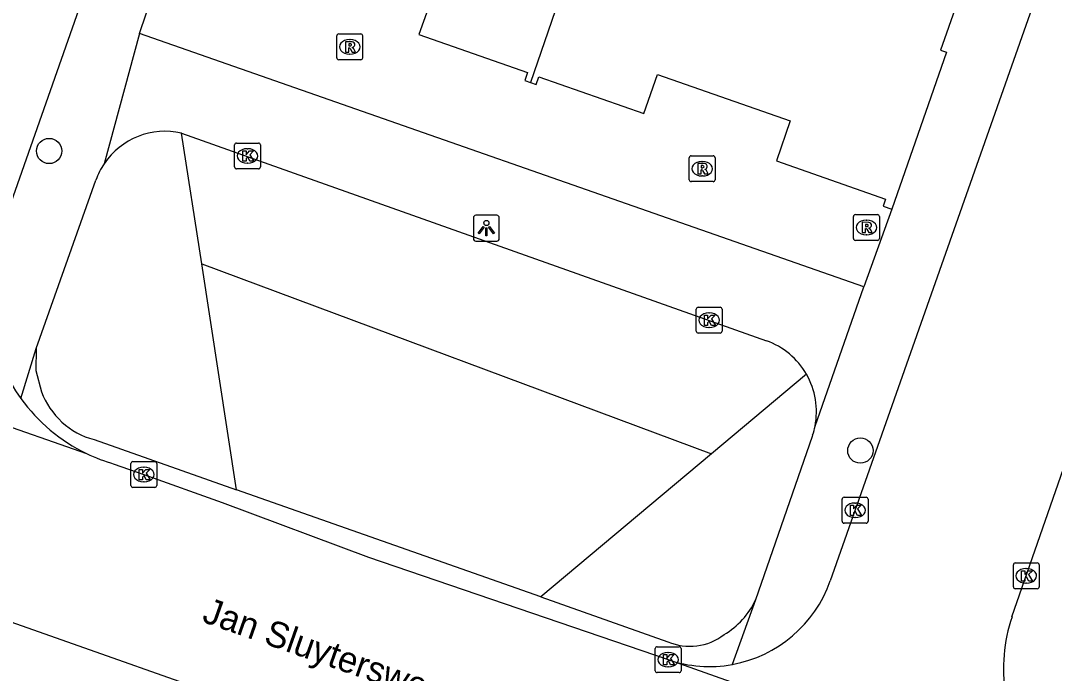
# Model space of a CAD drawing. Extents: x 163268 to 164360, y 381529 to 382285.
# Drawn here: x 163770.78 to 163810.76, y 381848.7 to 381873.93 of the extents above; entities that cross this region are included whole.
import ezdxf

# ---------------------------------------------------------------- set-up
doc = ezdxf.new("R2010")
doc.units = 0
for name, color, linetype in [('IMGEO_Boom', 7, 'Continuous'), ('IMGEO_Groenvoorziening', 7, 'Continuous'), ('IMGEO_Kolk', 7, 'Continuous'), ('IMGEO_Lichtpunt', 7, 'Continuous'), ('IMGEO_Openbare_ruimte_label', 7, 'Continuous'), ('IMGEO_Pand', 7, 'Continuous'), ('IMGEO_Rijbaan_lokaal_open', 7, 'Continuous'), ('IMGEO_Rioolput', 7, 'Continuous'), ('IMGEO_Voetpad_open', 7, 'Continuous')]:
    doc.layers.add(name, color=color, linetype=linetype)

msp = doc.modelspace()

# ---------------------------------------------------------------- linework, layer by layer
at = {"layer": 'IMGEO_Boom'}
for centre in [(163771.878, 381868.895), (163803.255, 381857.31)]:
    msp.add_circle(centre, 0.489, dxfattribs=at)
at = {"layer": 'IMGEO_Groenvoorziening'}
for points in [[(163777.78, 381864.53), (163777.001, 381869.584)], [(163779.121, 381855.795), (163777.78, 381864.53)], [(163777.78, 381864.53), (163797.5, 381857.188)], [(163801.172, 381860.26), (163797.5, 381857.188)], [(163797.5, 381857.188), (163790.89, 381851.653)]]:
    msp.add_lwpolyline(points, dxfattribs=at)
at = {"layer": 'IMGEO_Kolk'}
for p, q in [((163779.05, 381868.277), (163779.05, 381869.129)), ((163779.125, 381869.203), (163779.977, 381869.203)), ((163779.538, 381868.983), (163779.563, 381868.983)), ((163780.051, 381869.129), (163780.051, 381868.277)), ((163779.977, 381868.203), (163779.125, 381868.203)), ((163779.561, 381868.423), (163779.536, 381868.423)), ((163796.904, 381861.927), (163796.904, 381862.779)), ((163796.979, 381862.853), (163797.831, 381862.853)), ((163797.392, 381862.633), (163797.417, 381862.633)), ((163797.905, 381862.779), (163797.905, 381861.927)), ((163797.415, 381862.073), (163797.39, 381862.073)), ((163797.831, 381861.853), (163796.979, 381861.853)), ((163775.116, 381856.885), (163775.968, 381856.885)), ((163775.041, 381855.959), (163775.041, 381856.811)), ((163775.529, 381856.665), (163775.554, 381856.665)), ((163776.042, 381856.811), (163776.042, 381855.959)), ((163775.552, 381856.105), (163775.527, 381856.105)), ((163775.968, 381855.885), (163775.116, 381855.885)), ((163802.55, 381854.577), (163802.55, 381855.429)), ((163802.625, 381855.503), (163803.477, 381855.503)), ((163803.038, 381855.283), (163803.063, 381855.283)), ((163803.551, 381855.429), (163803.551, 381854.577)), ((163803.477, 381854.503), (163802.625, 381854.503)), ((163803.061, 381854.723), (163803.036, 381854.723)), ((163809.172, 381852.04), (163809.172, 381852.892)), ((163809.247, 381852.966), (163810.099, 381852.966)), ((163810.173, 381852.892), (163810.173, 381852.04)), ((163809.66, 381852.746), (163809.685, 381852.746)), ((163809.683, 381852.186), (163809.658, 381852.186)), ((163810.099, 381851.966), (163809.247, 381851.966)), ((163795.395, 381849.726), (163796.247, 381849.726)), ((163795.32, 381848.8), (163795.32, 381849.652)), ((163795.808, 381849.506), (163795.833, 381849.506)), ((163796.321, 381849.652), (163796.321, 381848.8)), ((163795.831, 381848.946), (163795.806, 381848.946)), ((163796.247, 381848.726), (163795.395, 381848.726))]:
    msp.add_line(p, q, dxfattribs=at)
for points in [[(163779.05, 381868.277), (163779.05, 381869.129)], [(163779.125, 381869.203), (163779.977, 381869.203)], [(163779.371, 381868.903), (163779.494, 381868.903), (163779.494, 381868.752), (163779.624, 381868.903), (163779.788, 381868.903), (163779.642, 381868.752), (163779.795, 381868.503), (163779.643, 381868.503), (163779.558, 381868.667), (163779.494, 381868.6), (163779.494, 381868.503), (163779.371, 381868.503), (163779.371, 381868.903)], [(163780.051, 381869.129), (163780.051, 381868.277)], [(163779.977, 381868.203), (163779.125, 381868.203)], [(163796.904, 381861.927), (163796.904, 381862.779)], [(163796.979, 381862.853), (163797.831, 381862.853)], [(163797.225, 381862.553), (163797.348, 381862.553), (163797.348, 381862.402), (163797.478, 381862.553), (163797.642, 381862.553), (163797.496, 381862.402), (163797.649, 381862.153), (163797.497, 381862.153), (163797.412, 381862.317), (163797.348, 381862.25), (163797.348, 381862.153), (163797.225, 381862.153), (163797.225, 381862.553)], [(163797.905, 381862.779), (163797.905, 381861.927)], [(163797.831, 381861.853), (163796.979, 381861.853)], [(163775.116, 381856.885), (163775.968, 381856.885)], [(163775.041, 381855.959), (163775.041, 381856.811)], [(163775.362, 381856.585), (163775.485, 381856.585), (163775.485, 381856.434), (163775.615, 381856.585), (163775.779, 381856.585), (163775.633, 381856.434), (163775.786, 381856.185), (163775.634, 381856.185), (163775.549, 381856.349), (163775.485, 381856.282), (163775.485, 381856.185), (163775.362, 381856.185), (163775.362, 381856.585)], [(163776.042, 381856.811), (163776.042, 381855.959)], [(163775.968, 381855.885), (163775.116, 381855.885)], [(163802.55, 381854.577), (163802.55, 381855.429)], [(163802.625, 381855.503), (163803.477, 381855.503)], [(163803.551, 381855.429), (163803.551, 381854.577)], [(163802.871, 381855.203), (163802.994, 381855.203), (163802.994, 381855.052), (163803.124, 381855.203), (163803.288, 381855.203), (163803.142, 381855.052), (163803.295, 381854.803), (163803.143, 381854.803), (163803.058, 381854.967), (163802.994, 381854.9), (163802.994, 381854.803), (163802.871, 381854.803), (163802.871, 381855.203)], [(163803.477, 381854.503), (163802.625, 381854.503)], [(163809.172, 381852.04), (163809.172, 381852.892)], [(163809.247, 381852.966), (163810.099, 381852.966)], [(163810.173, 381852.892), (163810.173, 381852.04)], [(163809.493, 381852.666), (163809.616, 381852.666), (163809.616, 381852.515), (163809.746, 381852.666), (163809.91, 381852.666), (163809.764, 381852.515), (163809.917, 381852.266), (163809.765, 381852.266), (163809.68, 381852.43), (163809.616, 381852.363), (163809.616, 381852.266), (163809.493, 381852.266), (163809.493, 381852.666)], [(163810.099, 381851.966), (163809.247, 381851.966)], [(163795.395, 381849.726), (163796.247, 381849.726)], [(163795.32, 381848.8), (163795.32, 381849.652)], [(163795.641, 381849.426), (163795.764, 381849.426), (163795.764, 381849.275), (163795.894, 381849.426), (163796.058, 381849.426), (163795.912, 381849.275), (163796.065, 381849.026), (163795.913, 381849.026), (163795.828, 381849.19), (163795.764, 381849.123), (163795.764, 381849.026), (163795.641, 381849.026), (163795.641, 381849.426)], [(163796.321, 381849.652), (163796.321, 381848.8)], [(163796.247, 381848.726), (163795.395, 381848.726)]]:
    msp.add_lwpolyline(points, dxfattribs=at)
for centre, start, end in [((163779.127, 381869.127), 91.552, 178.448), ((163779.127, 381869.127), 91.552, 178.448), ((163779.975, 381869.127), 1.552, 88.448), ((163779.975, 381869.127), 1.552, 88.448), ((163779.127, 381868.279), 181.552, 268.448), ((163779.127, 381868.279), 181.552, 268.448), ((163779.975, 381868.279), 271.552, 358.448), ((163779.975, 381868.279), 271.552, 358.448), ((163796.981, 381862.777), 91.552, 178.448), ((163796.981, 381862.777), 91.552, 178.448), ((163797.829, 381862.777), 1.552, 88.448), ((163797.829, 381862.777), 1.552, 88.448), ((163796.981, 381861.929), 181.552, 268.448), ((163796.981, 381861.929), 181.552, 268.448), ((163797.829, 381861.929), 271.552, 358.448), ((163797.829, 381861.929), 271.552, 358.448), ((163775.118, 381856.809), 91.552, 178.448), ((163775.118, 381856.809), 91.552, 178.448), ((163775.966, 381856.809), 1.552, 88.448), ((163775.966, 381856.809), 1.552, 88.448), ((163775.118, 381855.961), 181.552, 268.448), ((163775.118, 381855.961), 181.552, 268.448), ((163775.966, 381855.961), 271.552, 358.448), ((163775.966, 381855.961), 271.552, 358.448), ((163802.627, 381855.427), 91.552, 178.448), ((163802.627, 381855.427), 91.552, 178.448), ((163803.475, 381855.427), 1.552, 88.448), ((163803.475, 381855.427), 1.552, 88.448), ((163802.627, 381854.579), 181.552, 268.448), ((163802.627, 381854.579), 181.552, 268.448), ((163803.475, 381854.579), 271.552, 358.448), ((163803.475, 381854.579), 271.552, 358.448), ((163809.249, 381852.89), 91.552, 178.448), ((163809.249, 381852.89), 91.552, 178.448), ((163810.097, 381852.89), 1.552, 88.448), ((163810.097, 381852.89), 1.552, 88.448), ((163809.249, 381852.042), 181.552, 268.448), ((163809.249, 381852.042), 181.552, 268.448), ((163810.097, 381852.042), 271.552, 358.448), ((163810.097, 381852.042), 271.552, 358.448), ((163795.397, 381849.65), 91.552, 178.448), ((163795.397, 381849.65), 91.552, 178.448), ((163796.245, 381849.65), 1.552, 88.448), ((163796.245, 381849.65), 1.552, 88.448), ((163795.397, 381848.802), 181.552, 268.448), ((163795.397, 381848.802), 181.552, 268.448), ((163796.245, 381848.802), 271.552, 358.448), ((163796.245, 381848.802), 271.552, 358.448)]:
    msp.add_arc(centre, 0.0765, start, end, dxfattribs=at)
for centre, major_axis, ratio, start_param, end_param in [((163779.537, 381868.703), (-0.387, 0.002), 0.722429, 4.712389, 7.853982), ((163779.562, 381868.703), (-0.39, 0.002), 0.717154, 1.570796, 4.712389), ((163797.391, 381862.353), (-0.387, 0.002), 0.722429, 4.712389, 7.853982), ((163797.416, 381862.353), (-0.39, 0.002), 0.717154, 1.570796, 4.712389), ((163775.528, 381856.385), (-0.387, 0.002), 0.722429, 4.712389, 7.853982), ((163775.553, 381856.385), (-0.39, 0.002), 0.717154, 1.570796, 4.712389), ((163803.037, 381855.003), (-0.387, 0.002), 0.722429, 4.712389, 7.853982), ((163803.062, 381855.003), (-0.39, 0.002), 0.717154, 1.570796, 4.712389), ((163809.659, 381852.466), (-0.387, 0.002), 0.722429, 4.712389, 7.853982), ((163809.684, 381852.466), (-0.39, 0.002), 0.717154, 1.570796, 4.712389), ((163795.807, 381849.226), (-0.387, 0.002), 0.722429, 4.712389, 7.853982), ((163795.832, 381849.226), (-0.39, 0.002), 0.717154, 1.570796, 4.712389)]:
    msp.add_ellipse(centre, major_axis=major_axis, ratio=ratio, start_param=start_param, end_param=end_param, dxfattribs=at)
at = {"layer": 'IMGEO_Lichtpunt'}
for p, q in [((163788.291, 381866.314), (163788.291, 381865.507)), ((163788.291, 381866.314), (163788.291, 381865.507)), ((163789.193, 381866.409), (163788.385, 381866.409)), ((163789.193, 381866.409), (163788.385, 381866.409)), ((163789.287, 381865.507), (163789.287, 381866.314)), ((163789.287, 381865.507), (163789.287, 381866.314)), ((163788.385, 381865.413), (163789.193, 381865.413)), ((163788.385, 381865.413), (163789.193, 381865.413))]:
    msp.add_line(p, q, dxfattribs=at)
for points in [[(163788.665, 381865.978), (163788.704, 381865.95), (163788.516, 381865.688), (163788.478, 381865.715), (163788.665, 381865.978)], [(163788.767, 381865.93), (163788.814, 381865.93), (163788.814, 381865.608), (163788.767, 381865.608), (163788.767, 381865.93)], [(163788.877, 381865.95), (163788.915, 381865.977), (163789.102, 381865.715), (163789.063, 381865.687), (163788.877, 381865.95)]]:
    msp.add_lwpolyline(points, dxfattribs=at)
msp.add_circle((163788.79, 381866.112), 0.0994, dxfattribs=at)
for centre, start, end in [((163788.385, 381866.314), 90, 180), ((163788.385, 381866.314), 90, 180), ((163789.193, 381866.314), 0, 90), ((163789.193, 381866.314), 0, 90), ((163788.385, 381865.507), 180, 270), ((163788.385, 381865.507), 180, 270), ((163789.193, 381865.507), 270, 0), ((163789.193, 381865.507), 270, 360)]:
    msp.add_arc(centre, 0.0946, start, end, dxfattribs=at)
at = {"layer": 'IMGEO_Pand'}
for points in [[(163793.764, 381881.031), (163790.492, 381871.546)], [(163776.402, 381876.494), (163776.751, 381876.372), (163776.86, 381876.683), (163781.149, 381875.183), (163781.673, 381876.678), (163786.715, 381874.914), (163786.184, 381873.395), (163790.382, 381871.926), (163790.275, 381871.622), (163790.492, 381871.546)], [(163807.537, 381876.168), (163806.358, 381872.797), (163806.591, 381872.716), (163804.468, 381866.646)], [(163790.492, 381871.546), (163790.711, 381871.47), (163790.814, 381871.764), (163794.885, 381870.34), (163795.413, 381871.851), (163800.545, 381870.055), (163800.005, 381868.511), (163804.227, 381867.035), (163804.132, 381866.763), (163804.468, 381866.646)]]:
    msp.add_lwpolyline(points, dxfattribs=at)
at = {"layer": 'IMGEO_Rijbaan_lokaal_open'}
for points in [[(163846.791, 381979.115), (163802.089, 381852.268)], [(163769.681, 381864.823), (163769.977, 381865.691), (163779.141, 381891.761), (163784.6, 381907.284)], [(163842.527, 381825.22), (163708.059, 381872.677), (163706.919, 381873.05)], [(163757.684, 381862.669), (163773.325, 381857.198)], [(163809.12, 381850.886), (163812.108, 381859.471), (163812.258, 381859.902)], [(163774.389, 381856.791), (163775.543, 381856.384), (163778.574, 381855.301), (163784.237, 381853.183), (163795.817, 381849.226)], [(163795.817, 381849.226), (163812.836, 381843.202)]]:
    msp.add_lwpolyline(points, dxfattribs=at)
for centre, radius, start, end in [((163776.262, 381863.284), 6.758, 166.838, 215.882), ((163776.244, 381863.265), 6.732, 215.8375, 244.3077), ((163776.245, 381863.236), 6.707, 244.1954, 253.939), ((163797.416, 381853.914), 4.954, 280.3113, 340.5916), ((163815.134, 381848.864), 6.344, 161.4202, 188.6801), ((163797.418, 381853.912), 4.952, 251.1415, 280.3008)]:
    msp.add_arc(centre, radius, start, end, dxfattribs=at)
at = {"layer": 'IMGEO_Rioolput'}
for p, q in [((163783.004, 381872.496), (163783.004, 381873.348)), ((163783.079, 381873.422), (163783.931, 381873.422)), ((163784.005, 381873.348), (163784.005, 381872.496)), ((163783.492, 381873.202), (163783.517, 381873.202)), ((163783.515, 381872.642), (163783.49, 381872.642)), ((163783.931, 381872.422), (163783.079, 381872.422)), ((163796.635, 381867.783), (163796.635, 381868.635)), ((163796.71, 381868.709), (163797.562, 381868.709)), ((163797.123, 381868.489), (163797.148, 381868.489)), ((163797.636, 381868.635), (163797.636, 381867.783)), ((163797.562, 381867.709), (163796.71, 381867.709)), ((163797.146, 381867.929), (163797.121, 381867.929)), ((163802.988, 381865.511), (163802.988, 381866.363)), ((163803.063, 381866.437), (163803.915, 381866.437)), ((163803.476, 381866.217), (163803.501, 381866.217)), ((163803.989, 381866.363), (163803.989, 381865.511)), ((163803.915, 381865.437), (163803.063, 381865.437)), ((163803.499, 381865.657), (163803.474, 381865.657))]:
    msp.add_line(p, q, dxfattribs=at)
for points in [[(163783.004, 381872.496), (163783.004, 381873.348)], [(163783.079, 381873.422), (163783.931, 381873.422)], [(163784.005, 381873.348), (163784.005, 381872.496)], [(163783.593, 381873.12), (163783.341, 381873.122), (163783.341, 381872.722)], [(163783.341, 381872.722), (163783.465, 381872.722), (163783.465, 381872.884), (163783.476, 381872.884)], [(163783.519, 381873.041), (163783.465, 381873.041), (163783.465, 381872.96)], [(163783.465, 381872.96), (163783.517, 381872.96)], [(163783.523, 381872.855), (163783.594, 381872.722), (163783.734, 381872.722), (163783.669, 381872.848)], [(163783.931, 381872.422), (163783.079, 381872.422)], [(163796.635, 381867.783), (163796.635, 381868.635)], [(163796.71, 381868.709), (163797.562, 381868.709)], [(163797.636, 381868.635), (163797.636, 381867.783)], [(163797.224, 381868.407), (163796.972, 381868.409), (163796.972, 381868.009)], [(163796.972, 381868.009), (163797.096, 381868.009), (163797.096, 381868.171), (163797.107, 381868.171)], [(163797.15, 381868.328), (163797.096, 381868.328), (163797.096, 381868.247)], [(163797.096, 381868.247), (163797.148, 381868.247)], [(163797.154, 381868.142), (163797.225, 381868.009), (163797.365, 381868.009), (163797.3, 381868.135)], [(163797.562, 381867.709), (163796.71, 381867.709)], [(163802.988, 381865.511), (163802.988, 381866.363)], [(163803.063, 381866.437), (163803.915, 381866.437)], [(163803.577, 381866.135), (163803.325, 381866.137), (163803.325, 381865.737)], [(163803.989, 381866.363), (163803.989, 381865.511)], [(163803.325, 381865.737), (163803.449, 381865.737), (163803.449, 381865.899), (163803.46, 381865.899)], [(163803.503, 381866.056), (163803.449, 381866.056), (163803.449, 381865.975)], [(163803.449, 381865.975), (163803.501, 381865.975)], [(163803.507, 381865.87), (163803.578, 381865.737), (163803.718, 381865.737), (163803.653, 381865.863)], [(163803.915, 381865.437), (163803.063, 381865.437)]]:
    msp.add_lwpolyline(points, dxfattribs=at)
for centre, radius, start, end in [((163783.081, 381873.346), 0.0765, 91.552, 178.448), ((163783.081, 381873.346), 0.0765, 91.552, 178.448), ((163783.929, 381873.346), 0.0765, 1.552, 88.448), ((163783.929, 381873.346), 0.0765, 1.552, 88.448), ((163783.475, 381872.831), 0.0533, 26.0293, 88.6989), ((163783.501, 381873.149), 0.19, 274.7715, 282.9687), ((163783.525, 381872.945), 0.0964, 77.0061, 93.1865), ((163783.539, 381873.002), 0.0378, 276.6634, 79.6772), ((163783.592, 381873.01), 0.109, 350.3612, 89.416), ((163783.59, 381873.01), 0.112, 277.5842, 350.9817), ((163783.574, 381872.795), 0.108, 29.5134, 73.7905), ((163783.081, 381872.498), 0.0765, 181.552, 268.448), ((163783.081, 381872.498), 0.0765, 181.552, 268.448), ((163783.929, 381872.498), 0.0765, 271.552, 358.448), ((163783.929, 381872.498), 0.0765, 271.552, 358.448), ((163796.712, 381868.633), 0.0765, 91.552, 178.448), ((163796.712, 381868.633), 0.0765, 91.552, 178.448), ((163797.56, 381868.633), 0.0765, 1.552, 88.448), ((163797.56, 381868.633), 0.0765, 1.552, 88.448), ((163797.106, 381868.118), 0.0533, 26.0293, 88.6989), ((163797.132, 381868.436), 0.19, 274.7715, 282.9687), ((163797.156, 381868.232), 0.0964, 77.0061, 93.1865), ((163797.17, 381868.289), 0.0378, 276.6634, 79.6772), ((163797.223, 381868.297), 0.109, 350.3612, 89.416), ((163797.221, 381868.297), 0.112, 277.5842, 350.9817), ((163797.205, 381868.082), 0.108, 29.5134, 73.7905), ((163796.712, 381867.785), 0.0765, 181.552, 268.448), ((163796.712, 381867.785), 0.0765, 181.552, 268.448), ((163797.56, 381867.785), 0.0765, 271.552, 358.448), ((163797.56, 381867.785), 0.0765, 271.552, 358.448), ((163803.065, 381866.361), 0.0765, 91.552, 178.448), ((163803.065, 381866.361), 0.0765, 91.552, 178.448), ((163803.576, 381866.025), 0.109, 350.3612, 89.416), ((163803.913, 381866.361), 0.0765, 1.552, 88.448), ((163803.913, 381866.361), 0.0765, 1.552, 88.448), ((163803.459, 381865.846), 0.0533, 26.0293, 88.6989), ((163803.485, 381866.164), 0.19, 274.7715, 282.9687), ((163803.509, 381865.96), 0.0964, 77.0061, 93.1865), ((163803.523, 381866.017), 0.0378, 276.6634, 79.6772), ((163803.574, 381866.025), 0.112, 277.5842, 350.9817), ((163803.558, 381865.81), 0.108, 29.5134, 73.7905), ((163803.065, 381865.513), 0.0765, 181.552, 268.448), ((163803.065, 381865.513), 0.0765, 181.552, 268.448), ((163803.913, 381865.513), 0.0765, 271.552, 358.448), ((163803.913, 381865.513), 0.0765, 271.552, 358.448)]:
    msp.add_arc(centre, radius, start, end, dxfattribs=at)
for centre, major_axis, ratio, start_param, end_param in [((163783.491, 381872.922), (-0.387, 0.002), 0.722429, 4.712389, 7.853982), ((163783.516, 381872.922), (-0.39, 0.002), 0.717154, 1.570796, 4.712389), ((163797.122, 381868.209), (-0.387, 0.002), 0.722429, 4.712389, 7.853982), ((163797.147, 381868.209), (-0.39, 0.002), 0.717154, 1.570796, 4.712389), ((163803.475, 381865.937), (-0.387, 0.002), 0.722429, 4.712389, 7.853982), ((163803.5, 381865.937), (-0.39, 0.002), 0.717154, 1.570796, 4.712389)]:
    msp.add_ellipse(centre, major_axis=major_axis, ratio=ratio, start_param=start_param, end_param=end_param, dxfattribs=at)
at = {"layer": 'IMGEO_Voetpad_open'}
for points in [[(163775.374, 381873.443), (163776.402, 381876.494)], [(163775.374, 381873.443), (163774.008, 381868.401)], [(163803.394, 381863.644), (163775.374, 381873.443)], [(163777.001, 381869.584), (163799.621, 381861.56)], [(163771.375, 381861.258), (163773.691, 381867.772)], [(163804.468, 381866.646), (163803.394, 381863.644)], [(163801.502, 381858.259), (163803.394, 381863.644)], [(163770.786, 381859.323), (163771.375, 381861.258)], [(163771.375, 381861.258), (163771.37, 381860.409), (163771.581, 381859.587)], [(163773.615, 381857.733), (163779.121, 381855.795)], [(163801.41, 381857.906), (163801.395, 381857.861), (163799.205, 381851.54)], [(163790.89, 381851.653), (163779.121, 381855.795)], [(163790.89, 381851.653), (163795.813, 381849.92)], [(163799.205, 381851.54), (163798.303, 381849.04)]]:
    msp.add_lwpolyline(points, dxfattribs=at)
for centre, radius, start, end in [((163776.363, 381866.819), 2.837, 77.0155, 146.1179), ((163776.393, 381866.805), 2.87, 146.2049, 160.3012), ((163798.641, 381858.816), 2.913, 29.7082, 70.3544), ((163798.642, 381858.815), 2.914, 348.9999, 29.7297), ((163774.412, 381860.65), 3.024, 200.5781, 254.7233), ((163798.856, 381858.76), 2.693, 341.5085, 349.2762), ((163796.378, 381852.878), 3.127, 300.8501, 334.6745), ((163796.665, 381851.906), 2.161, 246.7835, 307.5641)]:
    msp.add_arc(centre, radius, start, end, dxfattribs=at)

# ---------------------------------------------------------------- texts
at = {"layer": 'IMGEO_Openbare_ruimte_label'}
msp.add_text('Jan Sluytersweg', height=1, rotation=340.6045, dxfattribs=at).set_placement((163777.751, 381850.705))

doc.saveas('drawing.dxf')
